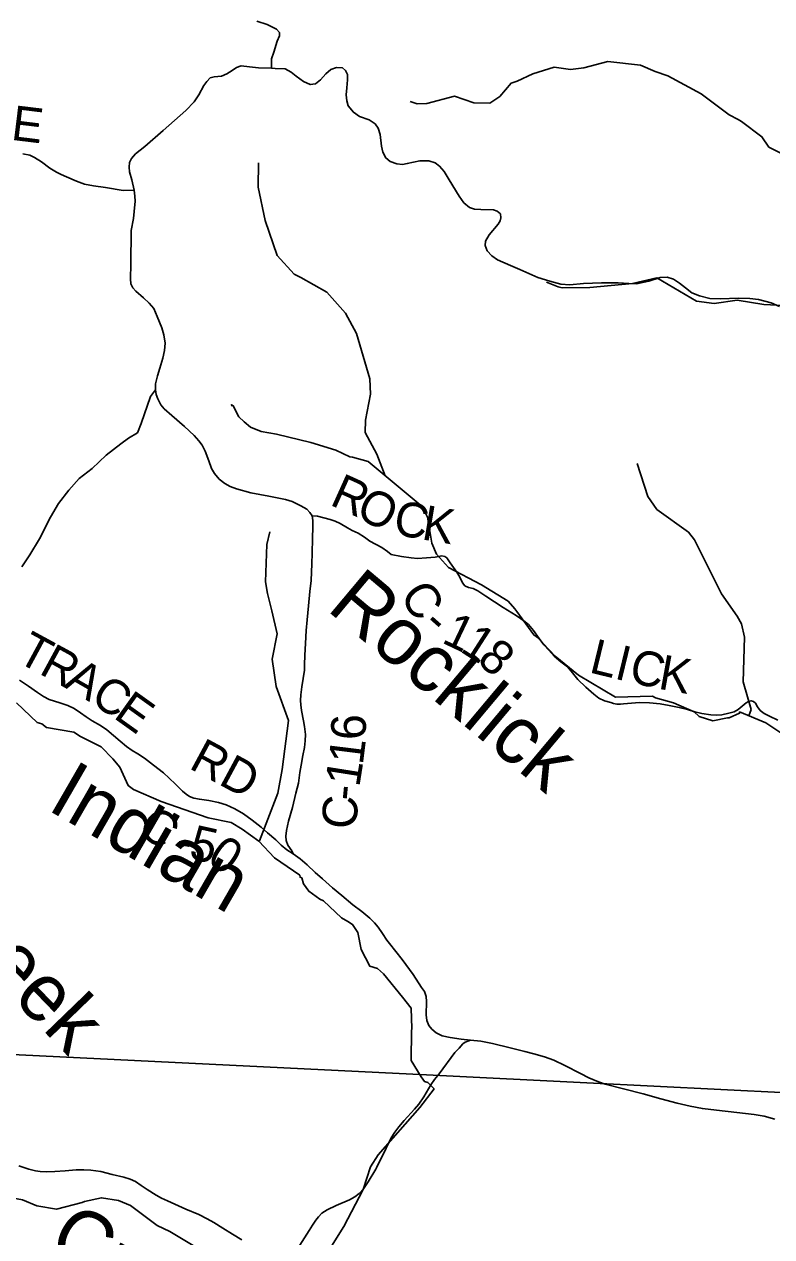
# Model space of a CAD drawing. Extents: x -1.8 to 75.7, y -2 to 25.
# Drawn here: x 3.751 to 4.973, y 16.983 to 18.965 of the extents above; entities that cross this region are included whole.
import ezdxf

# ---------------------------------------------------------------- set-up
doc = ezdxf.new("R2010")
doc.units = 0
for name, color, linetype in [('GM_X_County_Road', 7, 'Continuous'), ('GM_X_County_Road_Text', 7, 'Continuous'), ('GM_X_Minor_River', 7, 'Continuous'), ('GM_X_Minor_River_Text', 7, 'Continuous'), ('GM_X_State_Route', 7, 'Continuous'), ('GM_X_Township', 7, 'Continuous'), ('GM_X_Township_Road', 7, 'Continuous'), ('GM_X_Township_Road_Text', 7, 'Continuous'), ('GM_X_Township_ROW', 7, 'Continuous')]:
    doc.layers.add(name, color=color, linetype=linetype)

msp = doc.modelspace()

# ---------------------------------------------------------------- linework, layer by layer
at = {"layer": 'GM_X_County_Road'}
for points in [[(4.1907, 17.6088), (4.1884, 17.6138), (4.182, 17.6229), (4.1792, 17.6306), (4.1787, 17.6378), (4.1796, 17.6471), (4.1829, 17.6622), (4.1895, 17.6845), (4.1952, 17.7078), (4.1992, 17.7245), (4.2017, 17.7417), (4.2036, 17.754), (4.2067, 17.7696), (4.2093, 17.7826), (4.2105, 17.7934), (4.2107, 17.8042), (4.2093, 17.8169), (4.2078, 17.8266), (4.2043, 17.8433), (4.203, 17.8524), (4.2028, 17.8596), (4.2034, 17.8687), (4.205, 17.8818), (4.2071, 17.8955), (4.2089, 17.9089), (4.2094, 17.9179), (4.2096, 17.9336), (4.2109, 17.9527), (4.2118, 17.9738), (4.2135, 17.9916), (4.2159, 18.0141), (4.2181, 18.0379), (4.2199, 18.0557), (4.2208, 18.0695), (4.2214, 18.0828), (4.2217, 18.1002), (4.2221, 18.1247), (4.223, 18.1435), (4.223, 18.1536), (4.2218, 18.1616), (4.218, 18.1672), (4.213, 18.1722), (4.2033, 18.178), (4.1889, 18.1848), (4.178, 18.188), (4.1509, 18.1936), (4.1213, 18.1991), (4.0981, 18.2056), (4.0877, 18.2094), (4.0791, 18.2144), (4.0698, 18.2212), (4.0619, 18.2307), (4.0569, 18.2388), (4.0526, 18.2512), (4.0468, 18.2673), (4.042, 18.2768), (4.0366, 18.284), (4.0287, 18.293), (4.0129, 18.3073), (3.9921, 18.3253), (3.9795, 18.3366), (3.974, 18.343), (3.9691, 18.3529), (3.9666, 18.3601), (3.9655, 18.3676), (3.9655, 18.3734), (3.9657, 18.3773), (3.9688, 18.3902), (3.9725, 18.403), (3.9772, 18.4193), (3.9801, 18.432), (3.9813, 18.4439), (3.9792, 18.4573), (3.9758, 18.469), (3.9684, 18.4875), (3.9625, 18.5004), (3.9553, 18.509), (3.9458, 18.5178), (3.9334, 18.5286), (3.9286, 18.5345), (3.925, 18.5408), (3.9243, 18.549), (3.9252, 18.5727), (3.9259, 18.628), (3.9295, 18.6477), (3.9307, 18.659), (3.932, 18.6759), (3.9316, 18.6843), (3.9305, 18.6938), (3.9267, 18.7109), (3.923, 18.7239), (3.9222, 18.7313), (3.923, 18.739), (3.926, 18.7456), (3.9326, 18.7533), (3.9478, 18.7651), (3.9781, 18.7915), (4.0152, 18.8242), (4.0285, 18.8383), (4.0364, 18.8496), (4.0447, 18.865), (4.0492, 18.8718), (4.0549, 18.8774), (4.0616, 18.8795), (4.0733, 18.8806), (4.0823, 18.884), (4.0906, 18.8895), (4.0981, 18.8945), (4.1055, 18.897), (4.1192, 18.8955), (4.1341, 18.8942), (4.1553, 18.8934), (4.1613, 18.8927), (4.1773, 18.8925), (4.1871, 18.8867), (4.1958, 18.8803), (4.2076, 18.8714), (4.2185, 18.8665), (4.2272, 18.868), (4.2353, 18.8744), (4.2441, 18.8842), (4.2522, 18.8914), (4.2614, 18.8946), (4.2712, 18.8938), (4.2765, 18.8897), (4.2793, 18.8829), (4.2797, 18.8744), (4.2782, 18.8613), (4.2772, 18.85), (4.2782, 18.84), (4.2804, 18.8319), (4.2893, 18.8214), (4.2989, 18.8142), (4.3152, 18.809), (4.3246, 18.8022), (4.3299, 18.7952), (4.3329, 18.7847), (4.335, 18.7661), (4.3371, 18.7559), (4.3423, 18.7467), (4.3495, 18.7407), (4.3602, 18.7371), (4.3694, 18.736), (4.3771, 18.7373), (4.3976, 18.7418), (4.4127, 18.742), (4.4227, 18.7388), (4.43, 18.7331), (4.4375, 18.7245), (4.446, 18.7106), (4.462, 18.684), (4.4697, 18.6733), (4.4789, 18.6654), (4.4872, 18.663), (4.4977, 18.6622), (4.5184, 18.662), (4.5241, 18.6598), (4.5295, 18.6551), (4.5305, 18.6489), (4.5293, 18.644), (4.5261, 18.6385), (4.5111, 18.621), (4.5054, 18.6107), (4.5049, 18.6037), (4.5079, 18.5945), (4.5156, 18.5864), (4.5246, 18.5802), (4.5461, 18.571), (4.5613, 18.564), (4.5907, 18.5512), (4.6102, 18.545), (4.6285, 18.5403), (4.643, 18.539), (4.6655, 18.5416), (4.6947, 18.5422), (4.7222, 18.5422), (4.7397, 18.5411), (4.7523, 18.5409), (4.7722, 18.5454), (4.791, 18.5512), (4.8023, 18.5518), (4.8125, 18.5486), (4.8228, 18.542), (4.8322, 18.5343), (4.8428, 18.5262), (4.8554, 18.5211), (4.8723, 18.517), (4.8892, 18.5162), (4.919, 18.5175), (4.9376, 18.5168), (4.9519, 18.5153), (4.9724, 18.5096), (4.9863, 18.504)], [(4.2218, 18.1616), (4.2307, 18.1609), (4.2514, 18.1557), (4.2593, 18.153), (4.2677, 18.1489), (4.2795, 18.1419), (4.2871, 18.1373), (4.2968, 18.1329), (4.3072, 18.1265), (4.3158, 18.1202), (4.3359, 18.1096), (4.3447, 18.1033), (4.3511, 18.0985), (4.368, 18.0949), (4.3834, 18.0927), (4.3942, 18.0915), (4.4089, 18.0929), (4.4227, 18.094), (4.4337, 18.096), (4.4385, 18.0951), (4.4419, 18.0931), (4.4473, 18.0845), (4.4586, 18.0694), (4.4633, 18.0613), (4.4676, 18.0518), (4.4715, 18.0473), (4.4773, 18.0445), (4.4852, 18.0427), (4.4929, 18.0387), (4.5056, 18.0299), (4.5343, 18.0116), (4.5553, 17.9985), (4.5679, 17.9899), (4.5756, 17.9838), (4.584, 17.9738), (4.5928, 17.961), (4.6005, 17.9506), (4.6088, 17.9418), (4.6178, 17.932), (4.6287, 17.923), (4.6393, 17.9146), (4.6454, 17.9074), (4.656, 17.8939), (4.6694, 17.8814), (4.6822, 17.8697), (4.6906, 17.8634), (4.7001, 17.8591), (4.7102, 17.8564), (4.7148, 17.8548), (4.7202, 17.8537), (4.7258, 17.8537), (4.7312, 17.8543), (4.757, 17.8561), (4.7733, 17.8559), (4.7907, 17.8541), (4.8056, 17.8514), (4.8221, 17.8482), (4.8358, 17.8448), (4.8474, 17.8408), (4.8593, 17.8383), (4.874, 17.8363), (4.8828, 17.8358), (4.8919, 17.8363), (4.9034, 17.839), (4.912, 17.8412), (4.9185, 17.8446), (4.9253, 17.8505), (4.9314, 17.8557), (4.9352, 17.8582), (4.9395, 17.8591), (4.9436, 17.8579), (4.9468, 17.855), (4.9501, 17.8491), (4.9547, 17.843), (4.9608, 17.8385), (4.9698, 17.8338), (4.9836, 17.8272)], [(4.4807, 17.3043), (4.4656, 17.3061), (4.4473, 17.3086), (4.4342, 17.3115), (4.4243, 17.3162), (4.4175, 17.3221), (4.4125, 17.3284), (4.4091, 17.3363), (4.408, 17.3456), (4.4089, 17.3675), (4.4082, 17.3757), (4.4053, 17.3836), (4.4005, 17.3906), (4.3868, 17.4116), (4.3691, 17.436), (4.3484, 17.4624), (4.3438, 17.468), (4.3368, 17.4789), (4.3298, 17.4891), (4.3235, 17.4963), (4.3163, 17.5035), (4.3029, 17.5144), (4.2883, 17.5257), (4.2704, 17.5406), (4.2551, 17.5534), (4.2388, 17.5679), (4.2268, 17.5785), (4.2135, 17.5909), (4.202, 17.6009), (4.1907, 17.6088), (4.1805, 17.6153), (4.171, 17.623), (4.1622, 17.6316), (4.1487, 17.6433), (4.1385, 17.6526), (4.1236, 17.6641), (4.1094, 17.6745), (4.0951, 17.6822), (4.0811, 17.689), (4.0685, 17.6926), (4.0526, 17.696), (4.0373, 17.698), (4.0283, 17.6998), (4.0208, 17.7028), (4.0154, 17.7066), (4.0097, 17.7116), (3.9982, 17.7226), (3.9878, 17.7326), (3.9786, 17.7412), (3.9623, 17.754), (3.9476, 17.7651), (3.9368, 17.7723), (3.9273, 17.7778), (3.9182, 17.7841), (3.9074, 17.7931), (3.8966, 17.8026), (3.8857, 17.8116), (3.8755, 17.8186), (3.862, 17.8265), (3.8518, 17.8331), (3.8426, 17.8396), (3.8326, 17.8464), (3.8222, 17.8512), (3.8089, 17.8557), (3.7917, 17.8613), (3.782, 17.8663), (3.7723, 17.8724), (3.7576, 17.8828), (3.7429, 17.8927)]]:
    msp.add_lwpolyline(points, dxfattribs=at)
at = {"layer": 'GM_X_Minor_River'}
for points in [[(4.9903, 18.7532), (4.9687, 18.7642), (4.9572, 18.7812), (4.9239, 18.8062), (4.9187, 18.8094), (4.9038, 18.8171), (4.858, 18.8516), (4.8033, 18.8811), (4.7827, 18.8878), (4.7589, 18.8981), (4.7054, 18.9043), (4.6661, 18.8942), (4.6445, 18.8911), (4.6178, 18.895), (4.5827, 18.8839), (4.557, 18.8722), (4.5471, 18.8687), (4.5286, 18.8473), (4.5124, 18.8364), (4.4864, 18.8365), (4.4546, 18.8478), (4.4092, 18.8355), (4.3933, 18.8353), (4.3821, 18.8387)], [(4.3412, 18.2269), (4.3276, 18.2623), (4.3084, 18.2979), (4.3087, 18.318), (4.3172, 18.3602), (4.3162, 18.3856), (4.2942, 18.4596), (4.2765, 18.4929), (4.2455, 18.5273), (4.2029, 18.5514), (4.1922, 18.5566), (4.1647, 18.5873), (4.145, 18.6445), (4.1333, 18.6991), (4.1338, 18.7386)], [(5.1675, 18.5618), (5.1189, 18.53), (5.1069, 18.519), (5.0863, 18.5124), (5.0781, 18.5066), (5.0602, 18.4992), (5.0344, 18.4973), (4.9927, 18.5055), (4.9606, 18.5069), (4.917, 18.514), (4.879, 18.5087), (4.8504, 18.5127), (4.7854, 18.5505), (4.7454, 18.5415), (4.6761, 18.5346), (4.6307, 18.5345), (4.6243, 18.5359), (4.6049, 18.5433)], [(4.3132, 18.2502), (4.2878, 18.2576), (4.2833, 18.258), (4.2606, 18.2686), (4.2194, 18.2814), (4.1634, 18.295), (4.1381, 18.2995), (4.1211, 18.3063), (4.1105, 18.3154), (4.1018, 18.3233), (4.0927, 18.3416), (4.0896, 18.3431), (4.0904, 18.3408)], [(5.0111, 17.7914), (4.9638, 17.8229), (4.9207, 17.841), (4.9207, 17.8387), (4.9037, 17.8315), (4.901, 17.8311), (4.8768, 17.8261), (4.8549, 17.8336), (4.8466, 17.8408), (4.8125, 17.8556), (4.7834, 17.8642), (4.7785, 17.8669), (4.718, 17.8649), (4.6571, 17.9008), (4.6189, 17.9319), (4.5902, 17.9626), (4.5841, 17.9668), (4.5565, 18.0051), (4.5531, 18.0093), (4.5421, 18.0218), (4.4986, 18.0487), (4.4445, 18.0771), (4.4252, 18.0987), (4.4172, 18.1169), (4.4104, 18.1595), (4.4017, 18.1766), (4.3132, 18.2502)], [(4.9359, 17.8346), (4.9397, 17.8447), (4.9269, 17.8902), (4.9291, 17.9631), (4.9241, 17.9851), (4.9171, 17.9972), (4.8911, 18.0339), (4.8473, 18.1222), (4.837, 18.1346), (4.7855, 18.172), (4.7706, 18.1932), (4.7532, 18.247)], [(4.1353, 17.6303), (4.1656, 17.708), (4.1724, 17.7469), (4.1828, 17.8267), (4.1629, 17.8824), (4.1563, 17.927), (4.1644, 17.9685), (4.1557, 18.006), (4.1486, 18.0344), (4.1454, 18.0538), (4.1473, 18.1145), (4.1524, 18.1353)], [(4.107, 17.6494), (4.0892, 17.66), (4.0514, 17.6679), (3.9746, 17.6947), (3.9293, 17.7139), (3.9206, 17.7204), (3.9073, 17.7508), (3.8959, 17.7644), (3.8766, 17.7838), (3.8418, 17.8015), (3.8381, 17.8038), (3.832, 17.8076), (3.7874, 17.8155), (3.7798, 17.8215), (3.7719, 17.8234), (3.7382, 17.8557)], [(4.2234, 16.9195), (4.2736, 16.9998), (4.3049, 17.0603), (4.317, 17.0972), (4.3294, 17.117), (4.3978, 17.1943), (4.4212, 17.2248), (4.411, 17.235), (4.4053, 17.2369), (4.4, 17.2445), (4.3837, 17.2711), (4.3844, 17.3194), (4.3848, 17.3232), (4.3836, 17.3566), (4.3696, 17.3748), (4.3382, 17.4128), (4.3287, 17.4215), (4.3163, 17.4252), (4.3019, 17.4526), (4.2965, 17.4803), (4.2878, 17.4936), (4.2803, 17.4981), (4.2697, 17.5042), (4.2405, 17.5323), (4.2341, 17.5345), (4.216, 17.5478), (4.2073, 17.5599), (4.2046, 17.5694), (4.202, 17.5705), (4.2016, 17.574), (4.1603, 17.6024), (4.1346, 17.6297), (4.107, 17.6494)], [(4.0627, 16.9472), (3.9889, 16.9912), (3.9681, 17.0014), (3.9243, 17.0339), (3.905, 17.0423), (3.877, 17.0467), (3.8494, 17.0402), (3.8456, 17.0387), (3.8033, 17.0279), (3.7712, 17.0332), (3.7481, 17.0434), (3.7216, 17.0479), (3.6993, 17.0566), (3.6668, 17.0637), (3.5772, 17.0829), (3.5095, 17.0899), (3.4476, 17.0925)]]:
    msp.add_lwpolyline(points, dxfattribs=at)
at = {"layer": 'GM_X_State_Route'}
for points in [[(4.326, 17.0935), (4.327, 17.0953), (4.343, 17.1276), (4.351, 17.1443), (4.3568, 17.1536), (4.3635, 17.1625), (4.3722, 17.173), (4.3891, 17.1912), (4.396, 17.1996), (4.4043, 17.2114), (4.4159, 17.2311), (4.422, 17.2397), (4.4272, 17.2465), (4.4294, 17.2494), (4.4553, 17.2839), (4.4619, 17.2914), (4.468, 17.298), (4.4718, 17.3012), (4.4807, 17.3043)], [(4.4807, 17.3043), (4.4974, 17.3025), (4.5164, 17.2986), (4.5453, 17.2916), (4.5693, 17.2855), (4.5844, 17.2821), (4.6016, 17.2772), (4.6169, 17.2715), (4.6352, 17.2627), (4.6608, 17.2498), (4.6745, 17.2428), (4.6874, 17.2374), (4.6994, 17.2331), (4.7012, 17.2324), (4.7308, 17.2248), (4.7631, 17.2164), (4.792, 17.2083), (4.8187, 17.201), (4.8401, 17.1961), (4.86, 17.1925), (4.8831, 17.1897), (4.9165, 17.1859), (4.9449, 17.1825), (4.9608, 17.1798), (4.9782, 17.1753)], [(3.7421, 17.099), (3.7581, 17.0933), (3.769, 17.0907), (3.7769, 17.0895), (3.7872, 17.0889), (3.8008, 17.0893), (3.8178, 17.0907), (3.8359, 17.0924), (3.8483, 17.0924), (3.8599, 17.0917), (3.8758, 17.0894), (3.8944, 17.0848), (3.9136, 17.0805), (3.9239, 17.0771), (3.9328, 17.0731), (3.9421, 17.0666), (3.9518, 17.06), (3.9664, 17.0506), (3.9752, 17.0461), (3.9851, 17.0417), (4.0153, 17.0277), (4.0362, 17.0191), (4.05, 17.0123), (4.0609, 17.0064), (4.0757, 16.9969), (4.0913, 16.9872), (4.1066, 16.9777)], [(4.217, 16.9933), (4.2223, 17.0016), (4.2278, 17.0102), (4.232, 17.0153), (4.2375, 17.0212), (4.2461, 17.0271), (4.2611, 17.0341), (4.2826, 17.0434), (4.2917, 17.0482), (4.2987, 17.0537), (4.3059, 17.0613), (4.3135, 17.0725), (4.326, 17.0935)], [(4.1976, 16.9629), (4.217, 16.9933)]]:
    msp.add_lwpolyline(points, dxfattribs=at)
at = {"layer": 'GM_X_Township'}
for points in [[(2.1, 17.3659), (3.1354, 17.3103), (3.6863, 17.2831), (4.4195, 17.2469), (4.6712, 17.2345), (5.2191, 17.2074), (5.4813, 17.1939), (6.252, 17.1543), (6.3199, 17.9861), (6.3212, 18.0078), (6.3226, 18.0577), (6.3233, 18.0805), (6.3259, 18.1065), (6.3299, 18.1515), (6.3889, 19.1678), (6.4185, 19.6642), (6.4493, 20.1816), (6.4874, 20.9)], [(6.0631, 14.1), (6.0891, 14.525), (6.1136, 14.9242), (6.1259, 15.1242), (6.1707, 15.8638), (6.1898, 16.179), (6.2265, 16.7539), (6.252, 17.1543), (5.4813, 17.1939), (5.2191, 17.2074), (4.6712, 17.2345), (4.4195, 17.2469), (3.6863, 17.2831), (3.1354, 17.3103), (2.1, 17.3659)]]:
    msp.add_lwpolyline(points, dxfattribs=at)
at = {"layer": 'GM_X_Township_Road'}
msp.add_lwpolyline([(3.7482, 18.7532), (3.76, 18.751), (3.7675, 18.7474), (3.7788, 18.7401), (3.7925, 18.7298), (3.8034, 18.7236), (3.8109, 18.7194), (3.82, 18.7157), (3.8361, 18.7087), (3.8496, 18.704), (3.8643, 18.7012), (3.8835, 18.6982), (3.9128, 18.6933), (3.9305, 18.6938)], dxfattribs=at)
at = {"layer": 'GM_X_Township_ROW'}
for points in [[(4.1312, 18.9702), (4.1482, 18.9647), (4.1634, 18.9574), (4.1683, 18.9516), (4.1685, 18.9463), (4.1647, 18.9378), (4.1591, 18.9196), (4.1553, 18.9089), (4.1553, 18.8934)], [(3.747, 18.0783), (3.7601, 18.0979), (3.7759, 18.1237), (3.7935, 18.1595), (3.807, 18.1815), (3.8236, 18.2032), (3.8406, 18.2228), (3.8621, 18.239), (3.885, 18.2608), (3.9088, 18.2791), (3.9214, 18.2884), (3.9358, 18.2974), (3.9418, 18.3123), (3.9571, 18.3565), (3.9655, 18.3676)]]:
    msp.add_lwpolyline(points, dxfattribs=at)

# ---------------------------------------------------------------- texts
at = {"layer": 'GM_X_County_Road_Text'}
for s, height, rotation, p in [('R', 0.0568, 335.7221, (4.2487, 18.1803)), ('O', 0.0568, 332.0338, (4.2903, 18.1615)), ('C', 0.0568, 349.6234, (4.3524, 18.1318)), ('K', 0.0568, 350.4358, (4.3992, 18.1233)), ('C', 0.0568, 303.6154, (4.3634, 18.0311)), ('-', 0.0568, 318.5246, (4.3998, 17.9801)), ('1', 0.0568, 334.5372, (4.4317, 17.9551)), ('T', 0.0568, 331.5142, (3.7359, 17.9247)), ('1', 0.0568, 327.2301, (4.4616, 17.941)), ('R', 0.0568, 331.4553, (3.7732, 17.9044)), ('8', 0.0568, 318.2232, (4.4892, 17.9235)), ('L', 0.0568, 346.3286, (4.673, 17.9059)), ('I', 0.0568, 346.3273, (4.7143, 17.8958)), ('C', 0.0568, 347.0681, (4.7378, 17.8901)), ('K', 0.0568, 349.7534, (4.7861, 17.8791)), ('A', 0.0568, 329.9809, (3.8139, 17.8823)), ('C', 0.0568, 326.58, (3.8564, 17.8577)), ('E', 0.0568, 324.4262, (3.8949, 17.8323)), ('6', 0.0568, 89.1677, (4.3093, 17.7947)), ('RD', 0.05682, 331.6659, (4.0183, 17.7497)), ('1', 0.0568, 82.8945, (4.3045, 17.7532)), ('1', 0.0568, 81.0335, (4.2987, 17.7167)), ('-', 0.0568, 84.6766, (4.2967, 17.6944)), ('C', 0.0568, 86.3678, (4.2938, 17.6482)), ('C', 0.0568, 321.4094, (3.9328, 17.6474)), ('5', 0.0568, 347.4153, (4.0183, 17.6014)), ('-', 0.0568, 348.5859, (3.9957, 17.606)), ('0', 0.0568, 325.0216, (4.0471, 17.5962))]:
    msp.add_text(s, height=height, rotation=rotation, dxfattribs=at).set_placement(p)
at = {"layer": 'GM_X_Minor_River_Text'}
for s, height, rotation, p in [('Rocklick', 0.0947, 319.9998, (4.2436, 18.0085)), ('Indian', 0.0947, 330.0018, (3.7861, 17.6822)), ('Creek', 0.0947, 314.0019, (3.5886, 17.5197)), ('Creek', 0.09469, 330.0049, (3.7854, 16.9604))]:
    msp.add_text(s, height=height, rotation=rotation, dxfattribs=at).set_placement(p)
at = {"layer": 'GM_X_Township_Road_Text'}
msp.add_text('E', height=0.0568, rotation=353.0467, dxfattribs=at).set_placement((3.7279, 18.7765))

doc.saveas('drawing.dxf')
